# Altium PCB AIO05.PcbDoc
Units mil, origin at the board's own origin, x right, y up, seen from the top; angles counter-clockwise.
Board outline 6000 x 4000 mil, 2 copper layers (Top Layer, Bottom Layer); 12 components, 12 nets, 59 pads, 2 vias.
Unrouted connection lines stored in the file: 38.
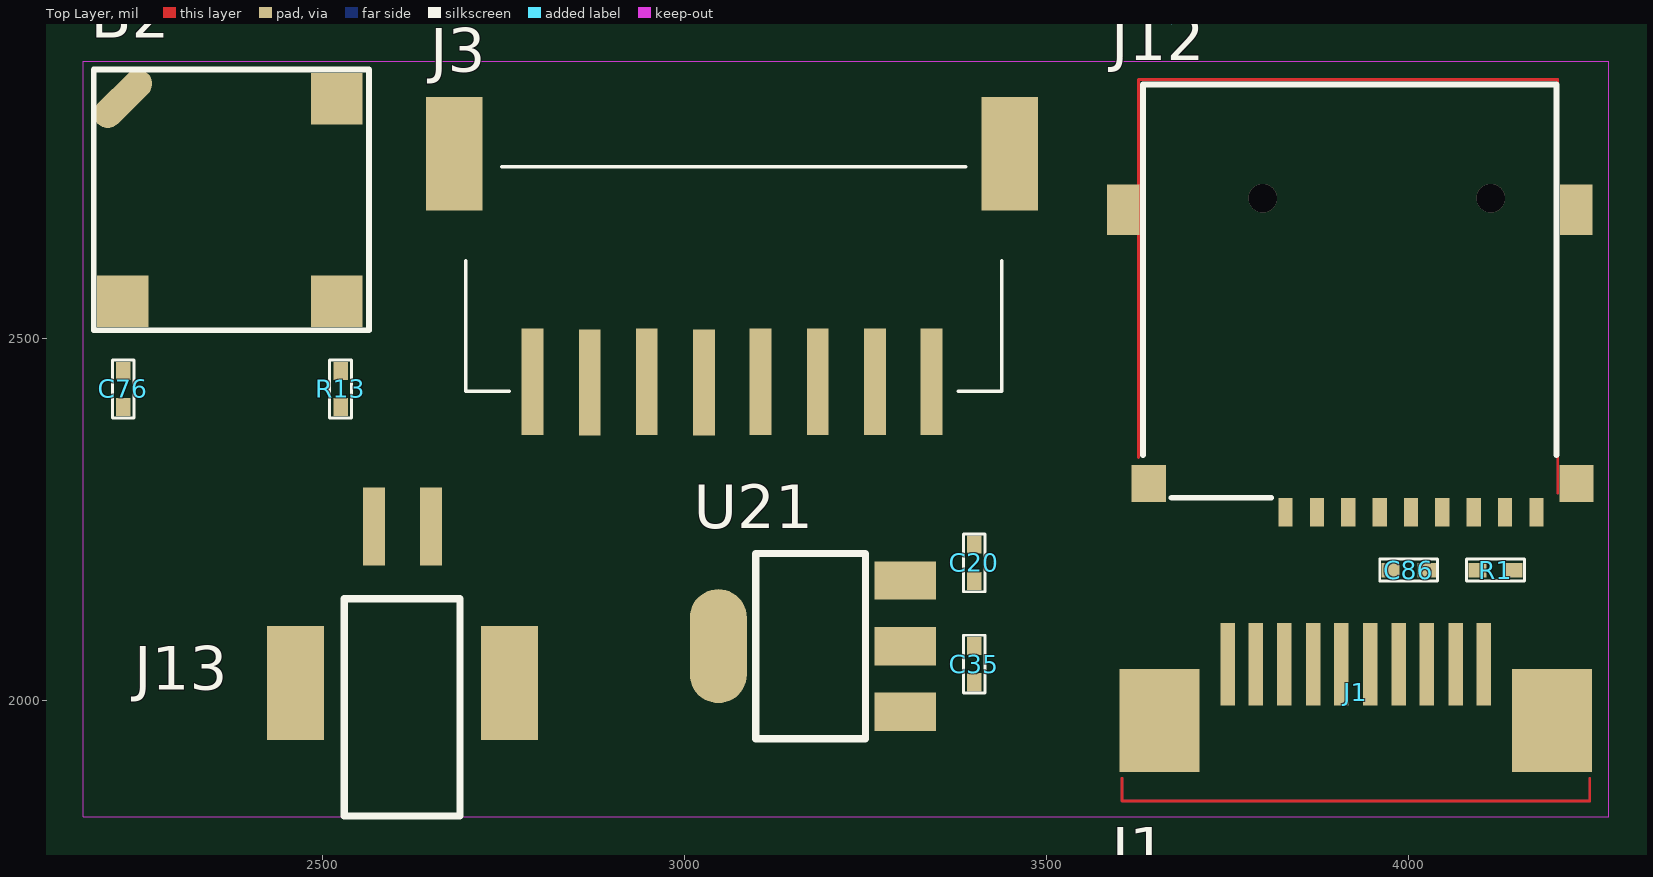
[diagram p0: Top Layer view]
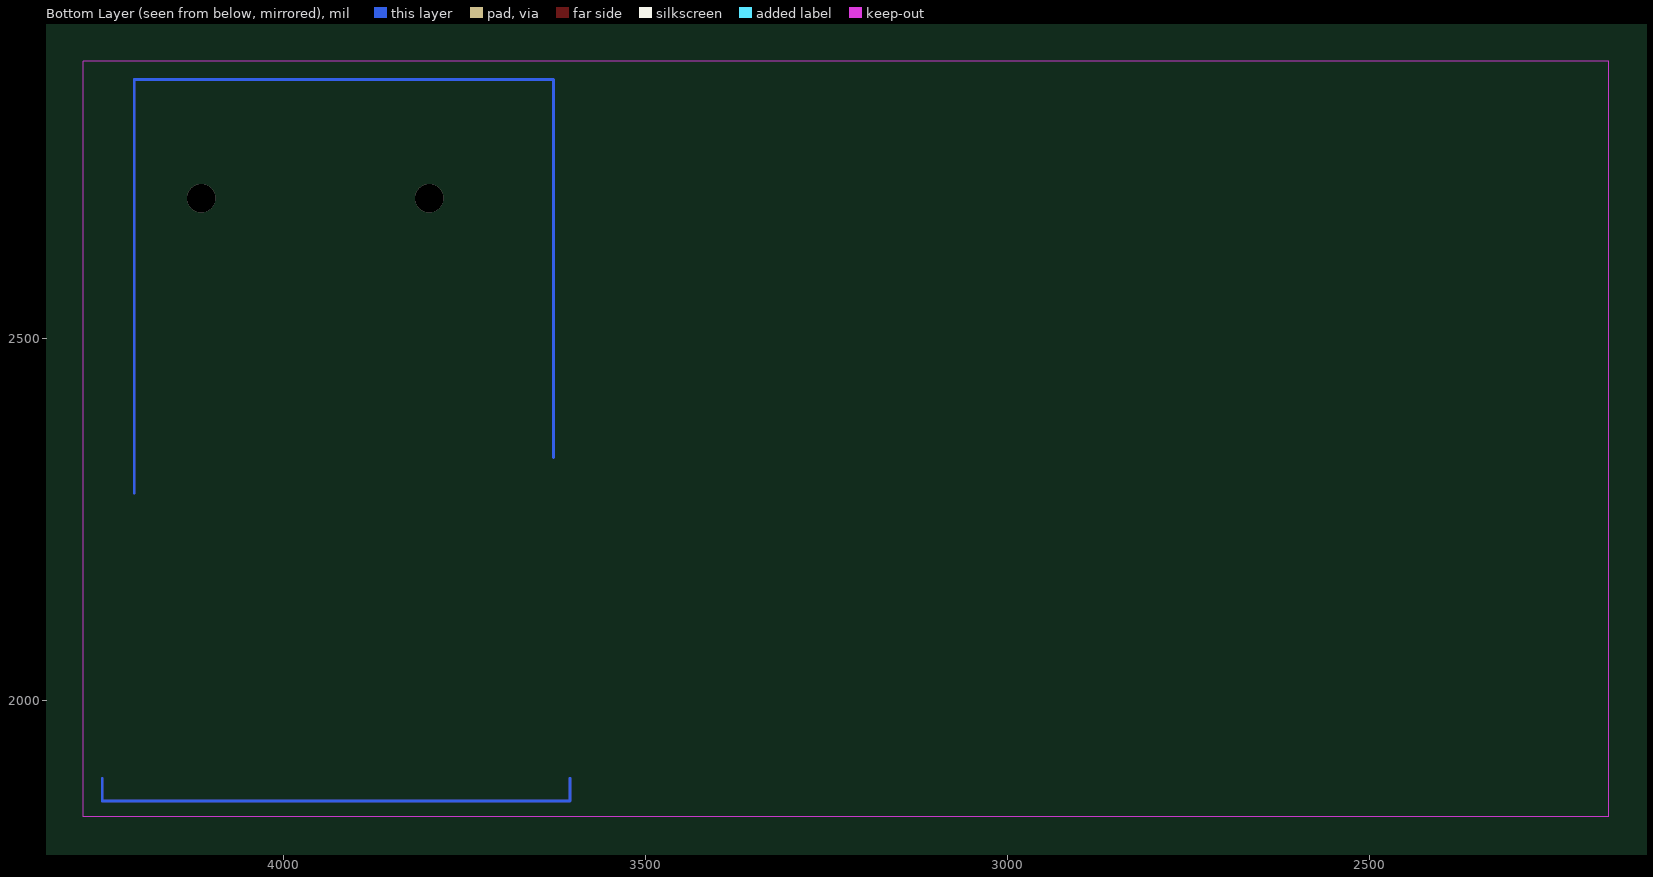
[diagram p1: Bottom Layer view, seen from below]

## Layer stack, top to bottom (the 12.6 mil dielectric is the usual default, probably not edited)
Top Layer: signal copper 1.4
Dielectric: dielectric 12.6, FR-4, Dk 4.8
Bottom Layer: signal copper 1.4

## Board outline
1000,1000 7000,1000 7000,5000 1000,5000

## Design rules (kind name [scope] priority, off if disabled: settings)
Clearance [All] p1: gap=10
PolygonConnect [All] p1: connectstyle=Relief reliefconductorwidth=10 reliefentries=4 polygonreliefangle="90 Angle"
RoomDefinition AIO05 [InComponentClass('AIO05')] p1: confinementstyle=ConfineIn formatcopy=TRUE lockcomponents=FALSE outline 7045,1055 10790,1055 10790,2025 7045,2025
RoutingVias [All] p1: holewidth=28 width=50 viastyle="Through Hole" minholewidth=28 minwidth=50 maxholewidth=28 maxwidth=50
SilkscreenOverComponentPads [All] p1: minsilkscreentomaskgap=10
SolderMaskExpansion [All] p1: expansion=4
Width [All] p1: maxlimit=10 minlimit=10 preferedwidth=10
27 further rules are at their usual default settings.

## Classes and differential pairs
component class AIO05: B2 C20 C35 C76 J1 J3 J12 J13 R13 U21

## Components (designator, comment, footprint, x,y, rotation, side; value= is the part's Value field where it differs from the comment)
B2 "KLJ-8530" BEEP 2224.33,2551.3 r0 top locked
C20 "4.7uF/6.3V" 0402A 3400,2165 r90 top
C35 "4.7uF/6.3V" 0402A 3400,2075 r270 top
C76 "0.1uF/16V" 0402A 2225,2455 r270 top
C86 "4.7uF/6.3V" 0402A 3975,2180 r0 top
J1 "FPC1.0-10下接" FPC1.0-10下接 3750,2050 r0 top locked
J3 "FPC2.0-8卧贴-带锁扣" FPC2.0-8卧贴-带锁扣 2790,2440 r180 top locked
J12 "TF卡" TF卡 3830,2260 r180 top locked
J13 "2.0-2语音插座" 2.0-2语音插座 2650,2240.32 r0 top locked
R1 "4.7K" 0402A 4145,2180 r180 top
R13 "39R" 0402A 2525,2455 r270 top
U21 "AMS1117-3.3" AMS1117-3.3 3305,2075 r90 top

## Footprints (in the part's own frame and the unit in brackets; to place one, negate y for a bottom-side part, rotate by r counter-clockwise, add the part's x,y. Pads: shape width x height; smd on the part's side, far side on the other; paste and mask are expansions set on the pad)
2.0-2语音插座 [mm]
  rect 0.76x2.73 smd: 1(0,0) 2(-2,0)
  rect 2x4 smd: 3(2.75,-5.5) 4(-4.75,-5.5)
  silkscreen extent -3.05,-10.16 1.02,-2.54
0402A [mil]
  rect 25x20 smd: 1(0,0) 2(50,0)
  silkscreen extent -15,-15 65,15
AMS1117-3.3 [mm]
  rect 1.35x2.15 smd: 1(-2.3,0) 2(0,0) 3(2.3,0)
  oval 4x2 smd: 4(0,6.56)
  silkscreen extent -3.25,1.4 3.25,5.25
BEEP [mm]
  rect 1.8x1.8 smd: 1(0,0) 2(7.5,0) 3(7.5,7.1)
  oval 2.5x1 smd rot 45: 4(0,7.1)
  silkscreen extent -1.02,-1.02 8.64,8.13
FPC1.0-10下接 [mil]
  rect 20x114 smd: 1(0,0) 2(39,0) 3(78,0) 4(118,0) 5(157,0) 6(197,0) 7(236,0) 8(275,0) 9(315,0) 10(354,0)
  rect 110x142 smd: 11(-94,-78) 12(448,-78)
FPC2.0-8卧贴-带锁扣 [mil]
  rect 30x147 smd: 1(0,0) 2(-79,1) 3(-158,0) 4(-237,1) 5(-315,0) 6(-394,0) 7(-473,0) 8(-551,0)
  rect 78x157 smd: 9(108,-315) 10(-659,-315)
  silkscreen extent -648,-297 92,13
TF卡 [mm]
  rect 0.5x1 smd: 1(0,0) 2(-1.1,0) 3(-2.2,0) 4(-3.3,0) 5(-4.4,0) 6(-5.5,0) 7(-6.6,0) 8(-7.7,0) 9(-8.8,0)
  rect 1.2x1.3 smd: 10(4.8,-1) 11(-10.2,-1)
  rect 1.143x1.778 smd: 12(5.7,-10.6) 13(-10.2,-10.6)
  silkscreen extent -9.5,-15 5,-0.5

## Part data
B2: library part BE
C20 C35 C76 C86: library part CAP, "Capacit"
J1: library part 1.
J13: library part 2.0
R1 R13: library part RE
U21: library part AMS111

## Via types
v1: diameter 39.37, hole 39.37, Top Layer to Bottom Layer, 2 vias

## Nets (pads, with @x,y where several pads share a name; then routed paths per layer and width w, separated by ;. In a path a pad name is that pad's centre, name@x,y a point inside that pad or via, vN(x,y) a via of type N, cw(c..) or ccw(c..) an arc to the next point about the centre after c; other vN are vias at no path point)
3.3V: C35.1 C86.1 J12.2 J12.4 R1.1 U21.2 U21.4
5V: B2.1 C20.1 C76.1 J1.1 J3.7 J3.8 U21.3
BEEP: J1.4 R13.2
CLK: J1.8 J12.5
CMD: J1.7 J12.3
DAT0: J1.9 J12.7 R1.2
GND: C20.2 C35.2 C76.2 C86.2 J1.10 J1.11 J1.12 J3.1 J3.2 J3.9 J3.10 J12.6 J12.10 J12.11 J13.3 J13.4 U21.1
NetB2_2: B2.2 R13.1
RXD: J1.5 J3.4
TXD: J1.6 J3.5
VOUTN: J1.2 J13.2
VOUTP: J1.3 J13.1
pads on no net: B2.3 B2.4 J3.3 J3.6 J12.1 J12.8 J12.9 J12.12 J12.13
copper on no net:
  other v1: 3798.5,2693.07 4113.46,2693.07

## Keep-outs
Keep-Out Layer:
  lines w0.04: 2169.84,1839.13 2169.84,2882.44 4276.14,2882.44 4276.14,1839.13 2169.84,1839.13

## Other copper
Multi-Layer:
  lines w3.94: 3604.33,1892.52 3604.33,1861.02 4250,1861.02 4250,1892.52 ; 3627.05,2335.51 3627.05,2857.17 4205.79,2857.17 4205.79,2286.3
  text "AIO05" at 2189.58,2294.06 h80

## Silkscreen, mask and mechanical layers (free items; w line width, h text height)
Top Solder:
  region: 2480.24,2515.87 2551.1,2515.87 2551.1,2586.73 2480.24,2586.73
Mechanical 1:
  circle w0.04: c2287.95,1957.24 r59.06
